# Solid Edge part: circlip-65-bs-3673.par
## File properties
Title: External circlip for shaft Ø65 - BS 3673
Author: TraceParts S.A.
Template: Iso Metric Part.par
Last saved by: Nimesh.N
Revision: 13
Application: TraceParts
Company: TraceParts S.A.
Density: 7833.000 kg/m^3
Accuracy: 0.990
REFERENCE: BS 3673 - d 65 - d2 62
STANDARD: BS 3673
DESIGN: External circlip for shaft Ø65 - BS 3673
OMNICLASS23: 23.13.23.11.13.25
TraceParts.PartStandardAcronym: BS
TraceParts.PartStatus: Published
TraceParts.PartNumber: 10-08012002-076217
TraceParts.InstanceId: 10-08012002-076217A8SIXD9RAH3GVU8Z1CW79VUO3
TraceParts.PartLanguage: en
TraceParts.PartTitle: External circlip
TraceParts.PartVersion: 1.3.0
TRACEPARTS: TRACEPARTS
TraceParts.ClassPath: BS:10-08012002-076217
Username: Nimesh.N
Material: Steel
Face Style: Steel
Fill Style: ANSI32(Steel)
Virtual Style: Machined steel
Grouping: Metals\Steel
LibraryName: Materials
Coef. of Thermal Exp: 1.3e-05
Thermal Conductivity: 32.0
Specific Heat: 481.0
Modulus of Elasticity: 199947953000.0
Poisson's Ratio: 0.29
Yield Stress: 262000766.0
Ultimate Stress: 358527364.0
Elongation: 0.0
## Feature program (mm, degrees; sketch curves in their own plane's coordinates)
body "unnamed Body 1"
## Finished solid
Body 1: solid body, 16 faces, 40 edges, 28 vertices.
  Faces by surface: cylinder 8, plane 8
  Edges by curve: line 24, circle 16
Bounding box of the edges (mm): 70.400 x 76.110 x 2.500, from (-35.2, -38.81, 0) to (35.2, 37.3, 2.5).
Cylindrical faces by radius (mm): R1.5 x2, R4.1163 x4, R31 x1, R35.2 x1
Planar faces by outward normal: +x 2, +z 1, -x 2, -y 2, -z 1
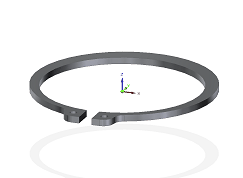
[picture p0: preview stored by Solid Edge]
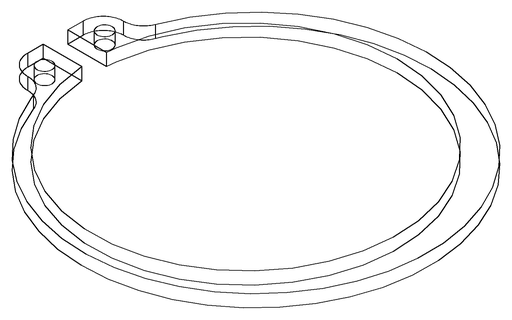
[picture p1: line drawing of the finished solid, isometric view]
